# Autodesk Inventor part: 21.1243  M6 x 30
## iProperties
Created: 2006-02
Part Number: 21.1243  M6 x 30
Material: Steel, Mild
Description: Cylinder Head Cap Screw
Document SubType Name: Modeling
Standard: DIN 7984
Designer: Andy Moles
Standards Organization: DIN
Language: en-US
Size Designation: M6 x 30
Categories: <MemberInstance><Categories><Category DisplayName="Fasteners" InternalName="e4da775c-781d-43d5-af7c-5136215cf5a6" Mnemonic="FSTN"><Category DisplayName="Bolts"
Density: 1 g/cm^3
Author: Andy Moles
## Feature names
1. Body [Revolution]
2. Slot [Extrusion]
3. Fillet1
4. Chamfer1
